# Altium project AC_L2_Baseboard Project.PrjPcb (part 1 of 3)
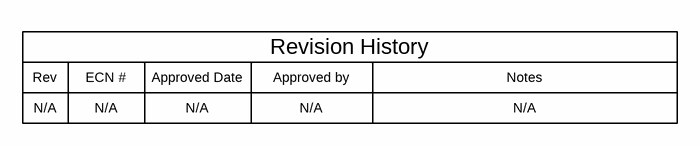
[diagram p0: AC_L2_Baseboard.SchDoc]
CopyrightYear: 2022; EVM_Orderable: N/A; PCB_Layout: R. Scibilia; PCB_Rev: C; PRJ_Engineer: R. Scibilia; PRJ_Number: PMP31161; PRJ_Title: 3-phase Flyback + POL and LDO; SCH_Rev: C; TechSupport: http://www.ti.com/support; TID: TIDA-010239
11 sheets, 511 parts. Net scope: flat (ports and power ports of the same name join across sheets).
Board file: AC_L2_Baseboard PCB.PcbDoc
Sheets:
  AC_L2_Baseboard.SchDoc
  AC_L2_Baseboard SCH-Flyback_PWR.SchDoc
  AC_L2_Baseboard SCH-POL_PWR.SchDoc
  AC_L2_Baseboard_Relay_Weld_Detect.SchDoc
  AC_L2_Baseboard_HPGP_ZC.SchDoc
  AC_L2_Baseboard_Pilot_Wire_ADC.SchDoc
  AC_L2_Baseboard_PlugLock.SchDoc
  AC_L2_Baseboard_RCD.SchDoc
  AC_L2_Baseboard_RCD_MCU.SchDoc
  AC_L2_Baseboard_Connectors.SchDoc
  AC_L2_Baseboard_Hardware.SchDoc

## Sheet AC_L2_Baseboard.SchDoc
size 431 x 279 mm; Date: Not shown in title block; ApprovedBy: Not shown in title block; CheckedBy: Not shown in title block; Author: Not shown in title block; CompanyName: Not shown in title block; Engineer: Not shown in title block; Organization: Not shown in title block; Address1: Not shown in title block; Address2: Not shown in title block; Address3: Not shown in title block; Address4: Not shown in title block; DocumentNumber: 1; Revision: Use project parameter SCH_Rev; SheetNumber: 1; SheetTotal: 11; PageSetup: Record=PageOptions¦CenterHorizontal=True¦CenterVertical=True¦PrintScale=1.00¦XCorrection=1.00¦YCorrection=1.00¦PrintKind=0¦BorderSize=5000000¦LeftOffset=0¦BottomOffset=0¦Orientation=2¦PaperLength=1000¦PaperWidth=1000¦Scale=100¦PaperSource=15¦PrintQuality=600¦MediaType=1¦DitherType=10¦PaperKind=Letter¦PrintScaleMode=1

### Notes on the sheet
- Rev
- N/A
- ECN #
- Approved Date
- Approved by
- Revision History
- Notes

## Sheet AC_L2_Baseboard SCH-Flyback_PWR.SchDoc
size 431 x 279 mm; Date: Not shown in title block; ApprovedBy: Not shown in title block; CheckedBy: Not shown in title block; Author: Not shown in title block; CompanyName: Not shown in title block; Engineer: Not shown in title block; Organization: Not shown in title block; Address1: Not shown in title block; Address2: Not shown in title block; Address3: Not shown in title block; Address4: Not shown in title block; DocumentNumber: 2; Revision: Use project parameter SCH_Rev; SheetNumber: 2; SheetTotal: 11; PageSetup: Record=PageOptions¦CenterHorizontal=True¦CenterVertical=True¦PrintScale=1.00¦XCorrection=1.00¦YCorrection=1.00¦PrintKind=0¦BorderSize=5000000¦LeftOffset=0¦BottomOffset=0¦Orientation=2¦PaperLength=1000¦PaperWidth=1000¦Scale=100¦PaperSource=15¦PrintQuality=600¦MediaType=1¦DitherType=10¦PaperKind=Letter¦PrintScaleMode=1
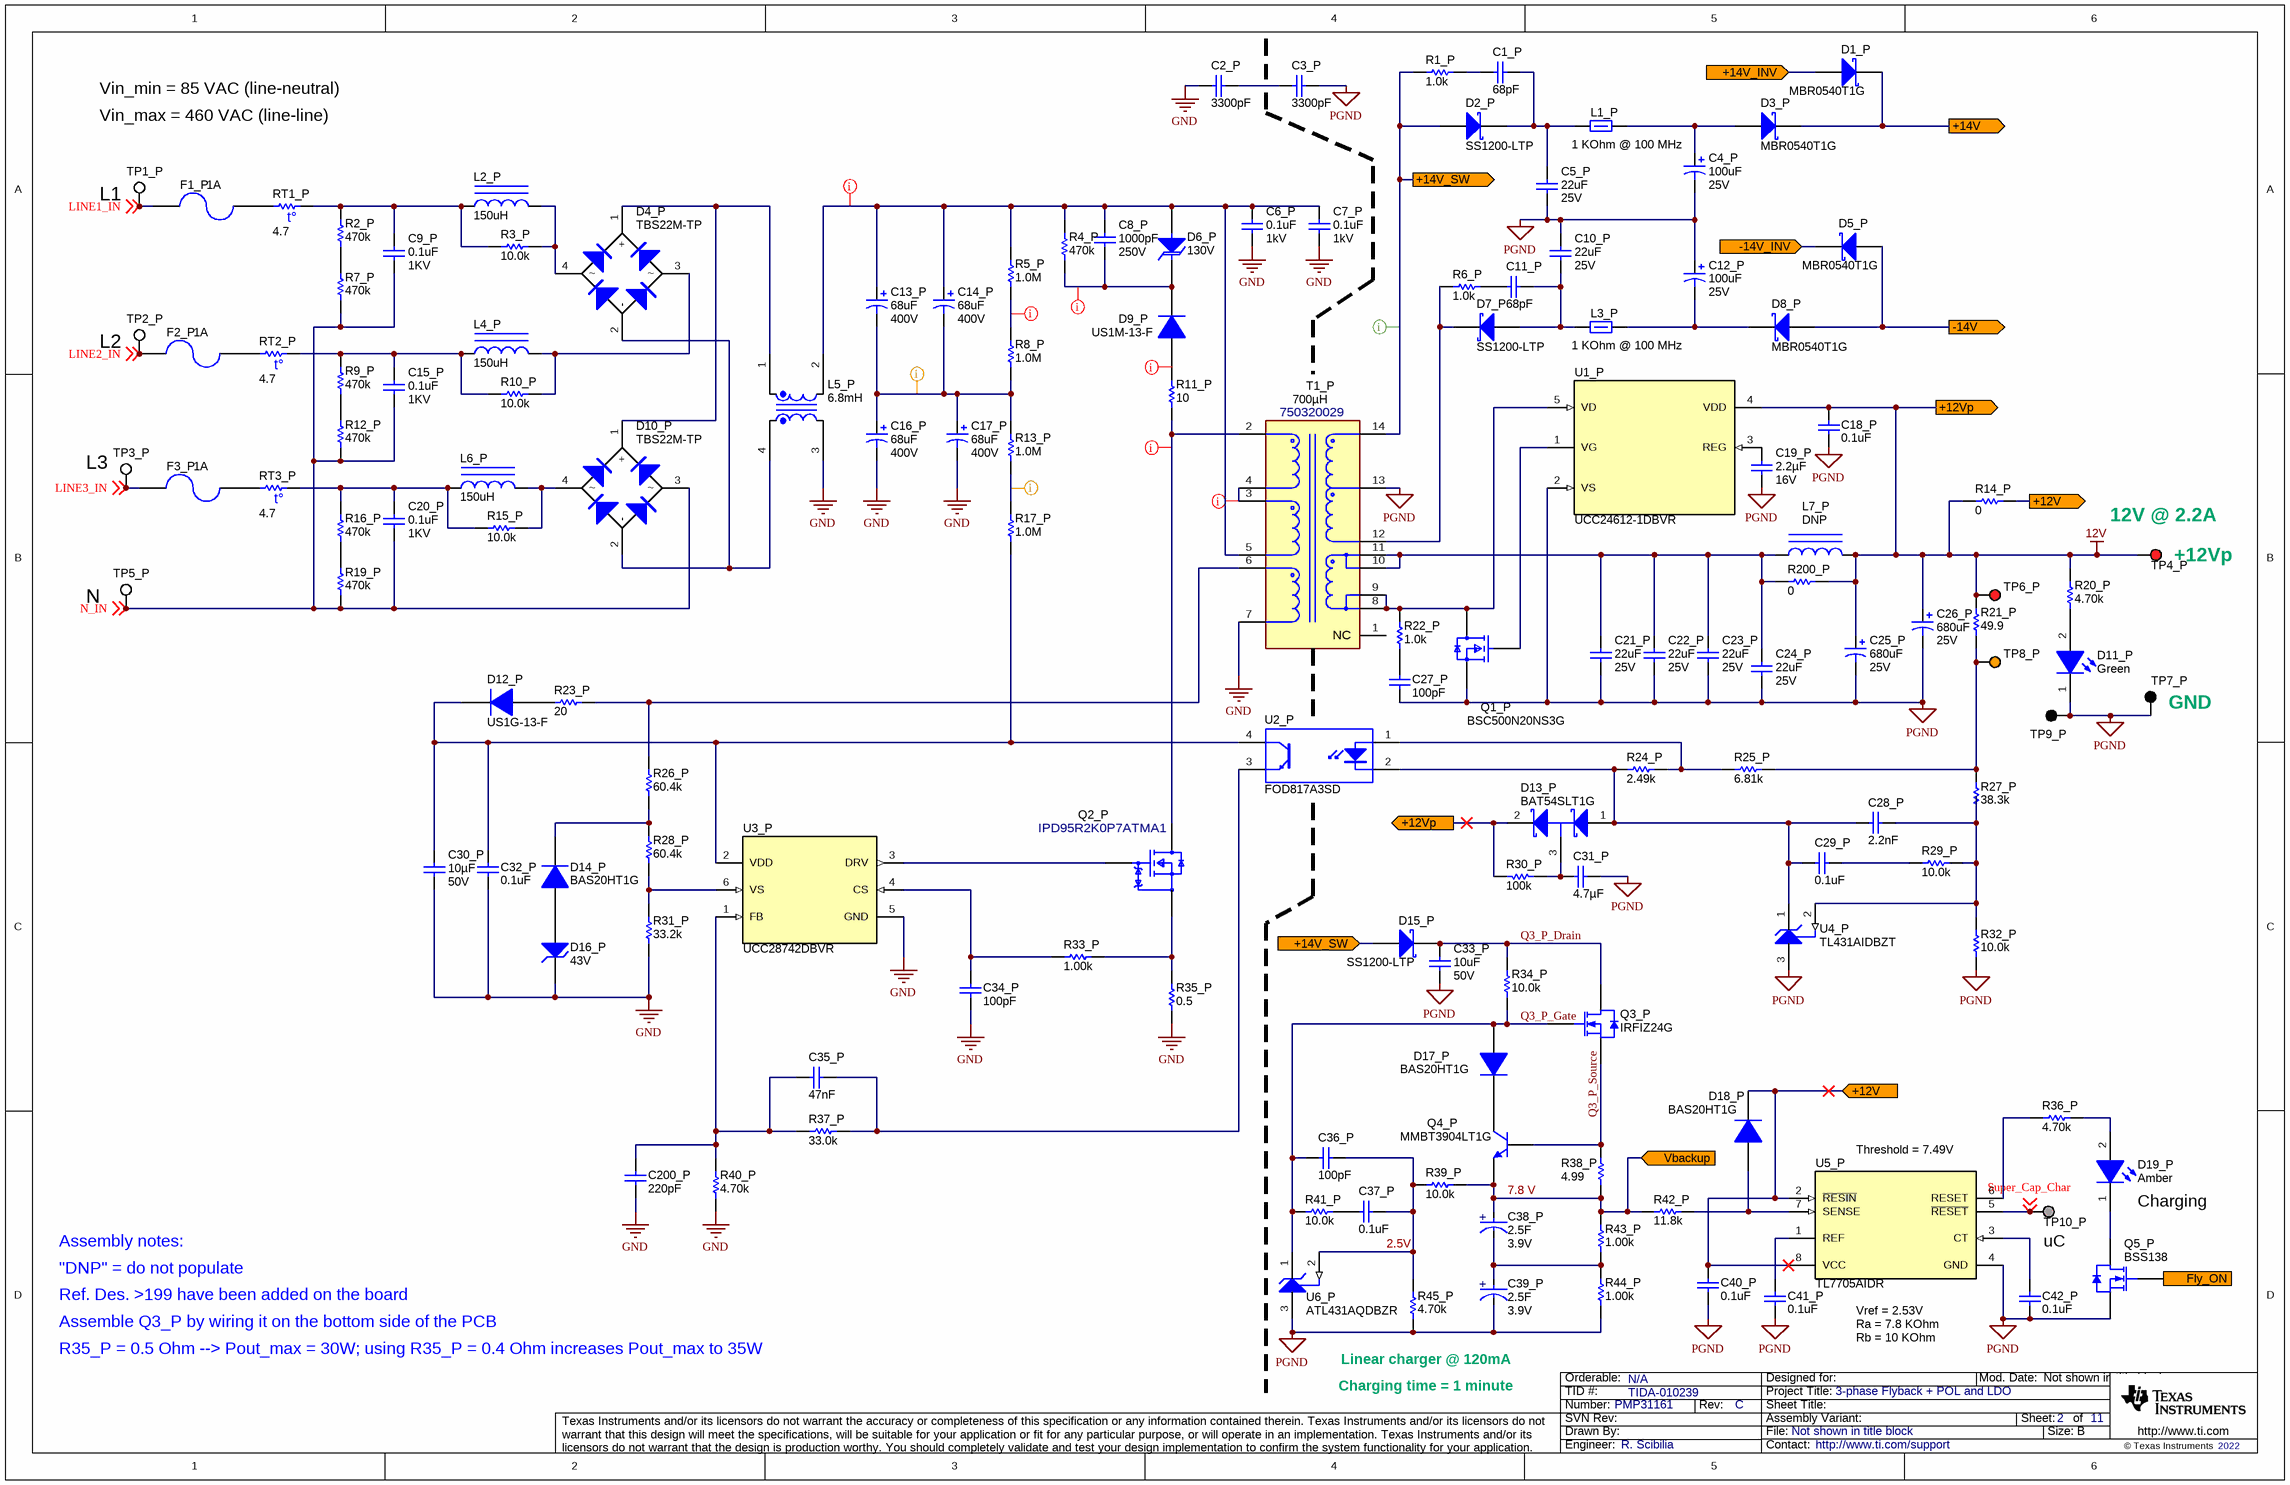
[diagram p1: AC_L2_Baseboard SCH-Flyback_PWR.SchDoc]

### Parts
C1_P  ValueDisplayed: 68pF  [0805_HV]  (hidden comment: GRM21A5C2E680JW01D)
C2_P  ValueDisplayed: 3300pF  [KX_1000x700]  (hidden comment: DE1E3KX332MN4AP01F)
C3_P  ValueDisplayed: 3300pF  [KX_1000x700]  (hidden comment: DE1E3KX332MN4AP01F)
C4_P  VDC_V: 25V  ValueDisplayed: 100uF  [Chemi-Con_630X1100]  (hidden comment: 860010473007)
C5_P  VDC_V: 25V  ValueDisplayed: 22uF  [1210_270]  (hidden comment: 885012109015)
C6_P  VDC_V: 1kV  ValueDisplayed: 0.1uF  [1812_254]  (hidden comment: C1812C104KDRAC7800)
C7_P  VDC_V: 1kV  ValueDisplayed: 0.1uF  [1812_254]  (hidden comment: C1812C104KDRAC7800)
C8_P  value 1000pF  VDC_V: 250V  [0805_HV]  (hidden comment: 885342207008)
C9_P  value 0.1uF  VDC_V: 1KV  [B32672P_1800x850x1450]  (hidden comment: 890493425009CS)
C10_P  VDC_V: 25V  ValueDisplayed: 22uF  [1210_270]  (hidden comment: 885012109015)
C11_P  ValueDisplayed: 68pF  [0805_HV]  (hidden comment: GRM21A5C2E680JW01D)
C12_P  VDC_V: 25V  ValueDisplayed: 100uF  [Chemi-Con_630X1100]  (hidden comment: 860010473007)
C13_P  VDC_V: 400V  ValueDisplayed: 68uF  [HW_1600x2500]  (hidden comment: 860021380017)
C14_P  VDC_V: 400V  ValueDisplayed: 68uF  [HW_1600x2500]  (hidden comment: 860021380017)
C15_P  value 0.1uF  VDC_V: 1KV  [B32672P_1800x850x1450]  (hidden comment: 890493425009CS)
C16_P  VDC_V: 400V  ValueDisplayed: 68uF  [HW_1600x2500]  (hidden comment: 860021380017)
C17_P  VDC_V: 400V  ValueDisplayed: 68uF  [HW_1600x2500]  (hidden comment: 860021380017)
C18_P  value 0.1uF  [0603]  (hidden comment: 885012206095)
C19_P  VDC_V: 16V  Cap_F: 2.2µF  [0603S]  (hidden comment: GRM188Z71C225KE43)
C20_P  value 0.1uF  VDC_V: 1KV  [B32672P_1800x850x1450]  (hidden comment: 890493425009CS)
C21_P  VDC_V: 25V  ValueDisplayed: 22uF  [1210_270]  (hidden comment: 885012109015)
C22_P  VDC_V: 25V  ValueDisplayed: 22uF  [1210_270]  (hidden comment: 885012109015)
C23_P  VDC_V: 25V  ValueDisplayed: 22uF  [1210_270]  (hidden comment: 885012109015)
C24_P  VDC_V: 25V  ValueDisplayed: 22uF  [1210_270]  (hidden comment: 885012109015)
C25_P  VDC_V: 25V  ValueDisplayed: 680uF  [Chemi-Con_1000x2000]  (hidden comment: 860040475009)
C26_P  VDC_V: 25V  ValueDisplayed: 680uF  [Chemi-Con_1000x2000]  (hidden comment: 860040475009)
C27_P  ValueDisplayed: 100pF  [0805_HV]  (hidden comment: GRM21A5C2E101JW01D)
C28_P  Cap_F: 2.2nF  [0603]  (hidden comment: 885012206085)
C29_P  value 0.1uF  [0603]  (hidden comment: 885012206095)
C30_P  VDC_V: 50V  ValueDisplayed: 10µF  [1206_190]  (hidden comment: 885012108022)
C31_P  Cap_F: 4.7µF  [0805_HV]  (hidden comment: 885012107018)
C32_P  value 0.1uF  [0603]  (hidden comment: 885012206095)
C33_P  VDC_V: 50V  ValueDisplayed: 10uF  [1206]  (hidden comment: 885012108022)
C34_P  value 100pF  [0603]  (hidden comment: 885012006057)
C35_P  Cap_F: 47nF  [0603]  (hidden comment: 885012206093)
C36_P  value 100pF  [0603]  (hidden comment: 885012006057)
C37_P  value 0.1uF  [0603]  (hidden comment: 885012206095)
C38_P  VDC_V: 3.9V  ValueDisplayed: 2.5F  [FP-PHVL-3R9V255-R_RADIAL-MFG]  (hidden comment: PHVL-3R9V255-R)
C39_P  VDC_V: 3.9V  ValueDisplayed: 2.5F  [FP-PHVL-3R9V255-R_RADIAL-MFG]  (hidden comment: PHVL-3R9V255-R)
C40_P  value 0.1uF  [0603]  (hidden comment: 885012206095)
C41_P  value 0.1uF  [0603]  (hidden comment: 885012206095)
C42_P  value 0.1uF  [0603]  (hidden comment: 885012206095)
C200_P  ValueDisplayed: 220pF  [0603]  (hidden comment: C0603C221J5GACTU)
D1_P  MBR0540T1G  [SOD-123]
D2_P  SS1200-LTP  [SMA]
D3_P  MBR0540T1G  [SOD-123]
D4_P  TBS22M-TP  [TBS4]
D5_P  MBR0540T1G  [SOD-123]
D6_P  value 130V  [SMC]  (hidden comment: SMCJ130A-TR)
D7_P  SS1200-LTP  [SMA]
D8_P  MBR0540T1G  [SOD-123]
D9_P  US1M-13-F  [SMA]
D10_P  TBS22M-TP  [TBS4]
D11_P  value Green  [WL_SMCW_RED_1206]  (hidden comment: 150120GS75000)
D12_P  US1G-13-F  [SMA]
D13_P  BAT54SLT1G  [SOT-23]
D14_P  BAS20HT1G  [SOD-323]
D15_P  SS1200-LTP  [SMA]
D16_P  value 43V  [SOD-323]  (hidden comment: BZX384C43-E3-08)
D17_P  BAS20HT1G  [SOD-323]
D18_P  BAS20HT1G  [SOD-323]
D19_P  value Amber  [WL_SMCW_RED_1206]  (hidden comment: 150120AS75000)
F1_P  Irating_A: 1A  [FUSE_0443]  (hidden comment: 0443001.DR)
F2_P  Irating_A: 1A  [FUSE_0443]  (hidden comment: 0443001.DR)
F3_P  Irating_A: 1A  [FUSE_0443]  (hidden comment: 0443001.DR)
L1_P  value 1 KOhm @ 100 MHz  [0805_HV]  (hidden comment: 74279205)
L2_P  value 150uH  [WE-TI_1014]  (hidden comment: 7447480151)
L3_P  value 1 KOhm @ 100 MHz  [0805_HV]  (hidden comment: 74279205)
L4_P  value 150uH  [WE-TI_1014]  (hidden comment: 7447480151)
L5_P  value 6.8mH  [Wurth_7446120047]  (hidden comment: 7446121007)
L6_P  value 150uH  [WE-TI_1014]  (hidden comment: 7447480151)
L7_P  DNP  [WE-PD2-S]
Q1_P  BSC500N20NS3G  [FP-BSC220N20NSFDATMA1_TSON-8-MFG]
Q2_P  IPD95R2K0P7ATMA1  [FP-IPD95R2K0P7ATMA1_DPAK-MFG]
Q3_P  IRFIZ24G  [TO-220FP]
Q4_P  MMBT3904LT1G  [SOT-23]
Q5_P  BSS138  [SOT-23]
R1_P  ValueDisplayed: 1.0k  [0805_HV]  (hidden comment: ERJ-6GEYJ102V)
R2_P  ValueDisplayed: 470k  [1206]  (hidden comment: CRCW1206470KJNEA)
R3_P  ValueDisplayed: 10.0k  [0805_HV]  (hidden comment: CRCW080510K0FKEA)
R4_P  ValueDisplayed: 470k  [1206]  (hidden comment: CRCW1206470KJNEA)
R5_P  ValueDisplayed: 1.0M  [1206]  (hidden comment: CRCW12061M00JNEA)
R6_P  ValueDisplayed: 1.0k  [0805_HV]  (hidden comment: ERJ-6GEYJ102V)
R7_P  ValueDisplayed: 470k  [1206]  (hidden comment: CRCW1206470KJNEA)
R8_P  ValueDisplayed: 1.0M  [1206]  (hidden comment: CRCW12061M00JNEA)
R9_P  ValueDisplayed: 470k  [1206]  (hidden comment: CRCW1206470KJNEA)
R10_P  ValueDisplayed: 10.0k  [0805_HV]  (hidden comment: CRCW080510K0FKEA)
R11_P  ValueDisplayed: 10  [1206]  (hidden comment: CRCW120610R0JNEA)
R12_P  ValueDisplayed: 470k  [1206]  (hidden comment: CRCW1206470KJNEA)
R13_P  ValueDisplayed: 1.0M  [1206]  (hidden comment: CRCW12061M00JNEA)
R14_P  ValueDisplayed: 0  [1206]  (hidden comment: RC1206JR-070RL)
R15_P  ValueDisplayed: 10.0k  [0805_HV]  (hidden comment: CRCW080510K0FKEA)
R16_P  ValueDisplayed: 470k  [1206]  (hidden comment: CRCW1206470KJNEA)
R17_P  ValueDisplayed: 1.0M  [1206]  (hidden comment: CRCW12061M00JNEA)
R19_P  ValueDisplayed: 470k  [1206]  (hidden comment: CRCW1206470KJNEA)
R20_P  ValueDisplayed: 4.70k  [0603]  (hidden comment: RC0603FR-074K7L)
R21_P  ValueDisplayed: 49.9  [0603]  (hidden comment: CRCW060349R9FKEA)
R22_P  ValueDisplayed: 1.0k  [1206]  (hidden comment: CRCW12061K00JNEA)
R23_P  ValueDisplayed: 20  [0805_HV]  (hidden comment: CRCW080520R0JNEA)
R24_P  ValueDisplayed: 2.49k  [0603]  (hidden comment: CRCW06032K49FKEA)
R25_P  ValueDisplayed: 6.81k  [0603]  (hidden comment: RC0603FR-076K81L)
R26_P  ValueDisplayed: 60.4k  [0805_HV]  (hidden comment: ERJ-6ENF6042V)
R27_P  ValueDisplayed: 38.3k  [0603]  (hidden comment: RC0603FR-0738K3L)
R28_P  ValueDisplayed: 60.4k  [0805_HV]  (hidden comment: ERJ-6ENF6042V)
R29_P  ValueDisplayed: 10.0k  [0603]  (hidden comment: RC0603FR-0710KL)
R30_P  ValueDisplayed: 100k  [0603]  (hidden comment: CRCW0603100KFKEA)
R31_P  ValueDisplayed: 33.2k  [0603]  (hidden comment: RC0603FR-0733K2L)
R32_P  ValueDisplayed: 10.0k  [0603]  (hidden comment: RC0603FR-0710KL)
R33_P  ValueDisplayed: 1.00k  [0603]  (hidden comment: CRCW06031K00FKEA)
R34_P  ValueDisplayed: 10.0k  [0603]  (hidden comment: RC0603FR-0710KL)
R35_P  ValueDisplayed: 0.5  [2010]  (hidden comment: CSRN2010FKR500)
R36_P  ValueDisplayed: 4.70k  [0603]  (hidden comment: RC0603FR-074K7L)
R37_P  ValueDisplayed: 33.0k  [0603]  (hidden comment: RC0603FR-0733KL)
R38_P  ValueDisplayed: 4.99  [0603]  (hidden comment: CRCW06034R99FKEA)
R39_P  ValueDisplayed: 10.0k  [0603]  (hidden comment: RC0603FR-0710KL)
R40_P  ValueDisplayed: 4.70k  [0603]  (hidden comment: RC0603FR-074K7L)
R41_P  ValueDisplayed: 10.0k  [0603]  (hidden comment: RC0603FR-0710KL)
R42_P  ValueDisplayed: 11.8k  [0603]  (hidden comment: RC0603FR-0711K8L)
R43_P  ValueDisplayed: 1.00k  [0603]  (hidden comment: CRCW06031K00FKEA)
R44_P  ValueDisplayed: 1.00k  [0603]  (hidden comment: CRCW06031K00FKEA)
R45_P  ValueDisplayed: 4.70k  [0603]  (hidden comment: RC0603FR-074K7L)
R200_P  ValueDisplayed: 0  [1206]  (hidden comment: RC1206JR-070RL)
RT1_P  value 4.7  [S153]  (hidden comment: B57153S0479M051)
RT2_P  value 4.7  [S153]  (hidden comment: B57153S0479M051)
RT3_P  value 4.7  [S153]  (hidden comment: B57153S0479M051)
T1_P  750320029  value 700µH  [FP-750320029_PTH14_32MM25_27MM05-MFG]
TP1_P  5012  [Keystone5012]  (value not drawn)
TP2_P  5012  [Keystone5012]  (value not drawn)
TP3_P  5012  [Keystone5012]  (value not drawn)
TP4_P  5010  [Keystone5010]  (value not drawn)
TP5_P  5012  [Keystone5012]  (value not drawn)
TP6_P  5000  [Keystone5000]  (value not drawn)
TP7_P  5011  [Keystone5011]  (value not drawn)
TP8_P  5003  [Keystone5003]  (value not drawn)
TP9_P  5001  [Keystone5001]  (value not drawn)
TP10_P  TP_SM_1MM  [TP_SM_1MM]  (value not drawn)  (no BOM)
U1_P  UCC24612-1DBVR  [DBV0005A_N]
U2_P  FOD817A3SD  [N04C]
U3_P  UCC28742DBVR  [DBV0006A_N]
U4_P  TL431AIDBZT  [DBZ0003A_N]
U5_P  TL7705AIDR  [D0008A_N]
U6_P  ATL431AQDBZR  [DBZ0003A_N]

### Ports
+12V (in), +12V (out), +12Vp (out), +14V (out), +14V_INV (in), +14V_SW (in), +14V_SW (out), -14V (out), -14V_INV (in), Fly_ON (in), Vbackup (in)

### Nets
12V: C18_P.1 C25_P.1(+) C26_P.1(+) D13_P.2(K) L7_P.2 R14_P.1 R20_P.2 R21_P.2 R30_P.1 R200_P.2 TP4_P.1 TP6_P.1 U1_P.4(VDD) ; port +12Vp  [project net 12V_In]
GND: C2_P.2 C6_P.2 C7_P.2 C16_P.2(-) C17_P.2(-) C30_P.2 C32_P.2 C34_P.2 C200_P.1 D16_P.1(K) L5_P.3 R31_P.1 R35_P.1 R40_P.1 T1_P.7 U3_P.5(GND)
PGND: C3_P.1 C4_P.2(-) C5_P.2 C10_P.1 C12_P.1(+) C18_P.2 C19_P.2 C21_P.2 C22_P.2 C23_P.2 C24_P.2 C25_P.2(-) C26_P.2(-) C27_P.2 C31_P.2 C33_P.2 C39_P.1(CATHODE) C40_P.2 C41_P.2 C42_P.2 D11_P.1(K) Q1_P.1-2-3(S) Q5_P.2(S) R32_P.1 R44_P.1 R45_P.1 T1_P.13 TP7_P.1 TP9_P.1 U1_P.2(VS) U4_P.3(ANODE) U5_P.4(GND) U6_P.3(ANODE)
+12V: C40_P.1 D18_P.1(K) R14_P.2 U5_P.2(~{RESIN}) U5_P.8(VCC) ; port +12V
+14V: D1_P.1(K) D3_P.1(K) ; port +14V
+14V_INV: D1_P.2(A) ; port +14V_INV
+14V_SW: D2_P.2(A) D15_P.2(A) R1_P.1 T1_P.14 ; port +14V_SW
-14V: D5_P.2(A) D8_P.2(A) ; port -14V
-14V_INV: D5_P.1(K) ; port -14V_INV
Fly_ON: Q5_P.1(G) ; port Fly_ON
LINE1_IN: F1_P.2 TP1_P.1 ; off-sheet LINE1_IN
LINE2_IN: F2_P.2 TP2_P.1 ; off-sheet LINE2_IN
LINE3_IN: F3_P.2 TP3_P.1 ; off-sheet LINE3_IN
N_IN: C9_P.2 C15_P.2 C20_P.2 D10_P.3 R7_P.1 R12_P.1 R19_P.1 TP5_P.1 ; off-sheet N_IN
Q3_P_Drain: C33_P.1 D15_P.1(K) Q3_P.2(D) R34_P.1
Q3_P_Gate: C36_P.1 D17_P.2(A) Q3_P.1(G) R34_P.2 R41_P.1 U6_P.1(CATHODE)
Q3_P_Source: Q3_P.3(S) Q4_P.1(B) R38_P.2
Super_Cap_Char: TP10_P.1 U5_P.5(~{RESET}) ; off-sheet Super_Cap_Char
Vbackup: C38_P.2(ANODE) Q4_P.2(E) R38_P.1 R39_P.1 R42_P.1 R43_P.2 ; port Vbackup
NetC1_P_1: C1_P.1 C5_P.1 D2_P.1(K) L1_P.1
NetC1_P_2: C1_P.2 R1_P.2
NetC2_P_1: C2_P.1 C3_P.2
NetC4_P_1: C4_P.1(+) D3_P.2(A) L1_P.2
NetC6_P_1: C6_P.1 C7_P.1 C8_P.1 C13_P.1(+) C14_P.1(+) D6_P.2(A) L5_P.2 R4_P.2 R5_P.2 T1_P.5
NetC8_P_2: C8_P.2 D6_P.1(K) D9_P.1(K) R4_P.1
NetC9_P_1: C9_P.1 L2_P.1 R2_P.2 R3_P.1 RT1_P.2
NetC10_P_2: C10_P.2 C11_P.1 D7_P.2(A) L3_P.1
NetC11_P_2: C11_P.2 R6_P.2
NetC12_P_2: C12_P.2(-) D8_P.1(K) L3_P.2
NetC13_P_2: C13_P.2(-) C14_P.2(-) C16_P.1(+) C17_P.1(+) R8_P.1 R13_P.2
NetC15_P_1: C15_P.1 L4_P.1 R9_P.2 R10_P.1 RT2_P.2
NetC19_P_1: C19_P.1 U1_P.3(REG)
NetC20_P_1: C20_P.1 L6_P.1 R15_P.1 R16_P.2 RT3_P.2
NetC21_P_1: C21_P.1 C22_P.1 C23_P.1 C24_P.1 L7_P.1 R200_P.1 T1_P.10 T1_P.11
NetC27_P_1: C27_P.1 R22_P.1
NetC28_P_1: C28_P.1 C29_P.1 D13_P.1(A) R24_P.2 U2_P.2(K) U4_P.1(CATHODE)
NetC28_P_2: C28_P.2 R27_P.1 R29_P.2 R32_P.2 U4_P.2(REF)
NetC29_P_2: C29_P.2 R29_P.1
NetC30_P_1: C30_P.1 C32_P.1 D12_P.1(K) R17_P.1 U2_P.4(C) U3_P.2(VDD)
NetC31_P_1: C31_P.1 D13_P.3(C) R30_P.2
NetC34_P_1: C34_P.1 R33_P.1 U3_P.4(CS)
NetC35_P_1: C35_P.1 R37_P.2 U2_P.3(E)
NetC35_P_2: C35_P.2 C200_P.2 R37_P.1 R40_P.2 U3_P.1(FB)
NetC36_P_2: C36_P.2 C37_P.2 R39_P.2 R45_P.2 U6_P.2(REF)
NetC37_P_1: C37_P.1 R41_P.2
NetC38_P_1: C38_P.1(CATHODE) C39_P.2(ANODE) R43_P.1 R44_P.2
NetC41_P_1: C41_P.1 U5_P.1(REF)
NetC42_P_1: C42_P.1 U5_P.3(CT)
NetD4_P_1: D4_P.1(+) D10_P.1(+) L5_P.1
NetD4_P_2: D4_P.2(-) D10_P.2(-) L5_P.4
NetD4_P_3: D4_P.3 L4_P.2 R10_P.2
NetD4_P_4: D4_P.4 L2_P.2 R3_P.2
NetD7_P_1: D7_P.1(K) R6_P.1 T1_P.12
NetD9_P_2: D9_P.2(A) R11_P.2
NetD10_P_4: D10_P.4 L6_P.2 R15_P.2
NetD11_P_2: D11_P.2(A) R20_P.1
NetD12_P_2: D12_P.2(A) R23_P.1
NetD14_P_1: D14_P.1(K) R26_P.1 R28_P.2
NetD14_P_2: D14_P.2(A) D16_P.2(A)
NetD17_P_1: D17_P.1(K) Q4_P.3(C)
NetD18_P_2: D18_P.2(A) R42_P.2 U5_P.7(SENSE)
NetD19_P_1: D19_P.1(K) Q5_P.3(D)
NetD19_P_2: D19_P.2(A) R36_P.1
NetF1_P_1: F1_P.1 RT1_P.1
NetF2_P_1: F2_P.1 RT2_P.1
NetF3_P_1: F3_P.1 RT3_P.1
NetQ1_P_4: Q1_P.4(G) U1_P.1(VG)
NetQ1_P_5-6-7-8: Q1_P.5-6-7-8(D) R22_P.2 T1_P.8 T1_P.9 U1_P.5(VD)
NetQ2_P_1: Q2_P.1(Gate) U3_P.3(DRV)
NetQ2_P_3: Q2_P.3(Source) R33_P.2 R35_P.2
NetQ2_P_4: Q2_P.4(Drain) R11_P.1 T1_P.2
NetR2_P_1: R2_P.1 R7_P.2
NetR5_P_1: R5_P.1 R8_P.2
NetR9_P_1: R9_P.1 R12_P.2
NetR13_P_1: R13_P.1 R17_P.2
NetR16_P_1: R16_P.1 R19_P.2
NetR21_P_1: R21_P.1 R25_P.2 R27_P.2 TP8_P.1
NetR23_P_2: R23_P.2 R26_P.2 T1_P.6
NetR24_P_1: R24_P.1 R25_P.1 U2_P.1(A)
NetR28_P_1: R28_P.1 R31_P.2 U3_P.6(VS)
NetR36_P_2: R36_P.2 U5_P.6(RESET)
NetT1_P_3: T1_P.3 T1_P.4

Not connected (* = marked no-connect by the designer): T1_P 1(NC)

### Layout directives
rule Clearance Constraint [Clearance = 30mil]: NetC6_P_1
rule Clearance Constraint [Clearance = 20mil]: NetC13_P_2, NetR13_P_1
rule Clearance Constraint [Clearance = 40mil]: NetC8_P_2, NetD9_P_2, NetQ2_P_4, NetR5_P_1, NetT1_P_3
rule Clearance Constraint [Clearance = 10mil]: +14V_SW

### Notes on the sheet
- Vin_min = 85 VAC (line-neutral)
- Vin_max = 460 VAC (line-line)
- (near TP1_P) L1
- (near TP2_P) L2
- (near TP3_P) L3
- (near TP4_P) 12V @ 2.2A
- (near TP4_P) +12Vp
- (near TP5_P) N
- (near TP7_P) GND
- (near U5_P) Threshold = 7.49V
- 7.8 V
- (near D19_P) Charging
- Assembly notes:
- Ref. Des. >199 have been added on the board
- "DNP" = do not populate
- 2.5V
- (near TP10_P) uC
- Assemble Q3_P by wiring it on the bottom side of the PCB
- R35_P = 0.5 Ohm --> Pout_max = 30W; using R35_P = 0.4 Ohm increases Pout_max to 35W
- (near R45_P) Linear charger @ 120mA
- (near U5_P) Vref = 2.53V
- Ra = 7.8 KOhm
- Rb = 10 KOhm
- Charging time = 1 minute

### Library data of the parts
C1_P C11_P = CMP-0008246-2: CAP, CERM, 68 pF, 250 V, +/- 5%, C0G/NP0, 0805; Manufacturer: MuRata; TaMin_C: -55°C; Polarized: N; SizeAreaWB_mm2: 6.75; Value1: Unknown; U/M: EA; Value: 68pF; TaMax_C: 125°C; SizeZ_mm: 1.45; SizeX_mm: 2; SizeY_mm: 1.25; Cap_Case: 0805; Value2: 250V; SizeArea_mm2: 2.5; AEC Category: Q200
C2_P C3_P = CMP-0009604-2: CAP, CERM, 3300 pF, 300 V, +/- 20%, E, D10xT7mm; Manufacturer: MuRata; TaMin_C: -40°C; Polarized: N; SizeAreaWB_mm2: 108; Value1: Unknown; U/M: EA; Value: 3300pF; TaMax_C: 125°C; SizeZ_mm: 13; SizeX_mm: 10; SizeY_mm: 7; Cap_Case: 10x7mm; Value2: 300V; SizeArea_mm2: 70; Cap_F: 3.3nF; AEC Category: Q200
C4_P C12_P = CMP-0010399-1: CAP, AL, 100 uF, 25 V, +/- 20%, TH; Manufacturer: Wuerth; TaMin_C: -40°C; Polarized: Y; SizeAreaWB_mm2: 68.89; Value1: Unknown; U/M: EA; Value: 100uF; TaMax_C: 105°C; SizeZ_mm: 12.5; SizeX_mm: 6.3; Cap_Case: 6.3x11; SizeArea_mm2: 39.69; CompType: Capacitor; AEC Qualified: N; Cap_F: 100µF; IRMS_A: 300mA; AEC Category: Q200
C5_P C10_P C21_P C22_P C23_P C24_P = CMP-0009224-2: CAP, CERM, 22 uF, 25 V, +/- 20%, X5R, 1210; Manufacturer: Wuerth; TaMin_C: -55°C; Polarized: N; SizeAreaWB_mm2: 14.7; Value1: Unknown; U/M: EA; Value: 22uF; TaMax_C: 85°C; SizeZ_mm: 2.7; SizeX_mm: 3.2; SizeY_mm: 2.5; Cap_Case: 1210; SizeArea_mm2: 8; Cap_F: 22µF; AEC Category: Q200
C6_P C7_P = CMP-0009326-2: CAP, CERM, 0.1 uF, 1000 V, +/- 10%, X7R, 1812; Manufacturer: Kemet; TaMin_C: -55°C; Polarized: N; SizeAreaWB_mm2: 23.1; Value1: Unknown; U/M: EA; Value: 0.1uF; TaMax_C: 125°C; SizeZ_mm: 2.54; SizeX_mm: 4.5; SizeY_mm: 3.2; Cap_Case: 1812; Value2: 1000V; SizeArea_mm2: 14.4; Cap_F: 100nF; AEC Category: Q200
C8_P = CMP-0008251-2: CAP, CERM, 1000 pF, 250 V, +/- 10%, X7R, 0805; Manufacturer: Wuerth; TaMin_C: -55°C; Polarized: N; SizeAreaWB_mm2: 6.75; Value1: Unknown; U/M: EA; TaMax_C: 125°C; SizeZ_mm: 1.45; SizeX_mm: 2; SizeY_mm: 1.25; Cap_Case: 0805; SizeArea_mm2: 2.5; Cap_F: 1nF; AEC Category: Q200
C9_P C15_P C20_P = CMP-0860409-1: CAP, Film, 0.1 µF, 1000 VDC,+/- 10%, TH; Manufacturer: Wuerth; SizeY_mm: 8.5; AEC Category: Q200; AEC Qualified: N; Cap_Case: 18x8.5x15mm; ValueDisplayed: 0.1µF; SizeArea_mm2: 153; SizeAreaWB_mm2: 210; SizeX_mm: 18; SizeZ_mm: 15; TaMin_C: -55°C; TaMax_C: 85°C; Cap_F: 100nF
C13_P C14_P C16_P C17_P = CMP-0009928-2: CAP, AL, 68 uF, 400 V, +/- 20%, 410 mA @ 120 Hz, TH; Manufacturer: Wuerth; TaMin_C: -40°C; Polarized: Y; SizeAreaWB_mm2: 324; U/M: EA; Value: 68uF; TaMax_C: 105°C; SizeZ_mm: 27; SizeX_mm: 16; Cap_Case: 16x25mm; SizeArea_mm2: 256; CompType: Capacitor; AEC Qualified: N; IRMS_A: 410mA
C18_P C29_P C32_P C37_P C40_P C41_P C42_P = CMP-0007044-5: CAP, CERM, 0.1 uF, 50 V, +/- 10%, X7R, 0603; Manufacturer: Wuerth; TaMin_C: -55°C; ESR_ohm: 29.6m; Polarized: N; SizeAreaWB_mm2: 4.68; Value1: 0.0296 ohm; U/M: EA; TaMax_C: 125°C; SizeZ_mm: 1; SizeX_mm: 1.6; SizeY_mm: 0.8; Value2: 50V; SizeArea_mm2: 1.28; Cap_F: 100nF; IRMS_A: 971.99mA; AEC Category: Q200
C19_P = CMP-0007499-4: CAP, CERM, 2.2 uF, 16 V, +/- 10%, X7R, 0603; Manufacturer: MuRata; TaMin_C: -55°C; Polarized: N; SizeAreaWB_mm2: 4.68; Value1: Unknown; U/M: EA; Value: 2.2uF; TaMax_C: 125°C; SizeZ_mm: 1; SizeX_mm: 1.6; SizeY_mm: 0.8; Cap_Case: 0603; SizeArea_mm2: 1.28; AEC Category: Q200
C25_P C26_P = CMP-0010412-1: CAP, AL, 680 uF, 25 V, +/- 20%, TH; Manufacturer: Wuerth; TaMin_C: -40°C; Polarized: Y; SizeAreaWB_mm2: 144; Value1: Unknown; U/M: EA; Value: 680uF; TaMax_C: 105°C; SizeZ_mm: 21.5; SizeX_mm: 10; Cap_Case: 10x20; SizeArea_mm2: 100; CompType: Capacitor; AEC Qualified: N; Cap_F: 680µF; IRMS_A: 1.4A
C27_P = CMP-0008236-2: CAP, CERM, 100 pF, 250 V, +/- 5%, C0G/NP0, 0805; Manufacturer: MuRata; TaMin_C: -55°C; Polarized: N; SizeAreaWB_mm2: 6.75; Value1: Unknown; U/M: EA; Value: 100pF; TaMax_C: 125°C; SizeZ_mm: 1.45; SizeX_mm: 2; SizeY_mm: 1.25; Cap_Case: 0805; Value2: 250V; SizeArea_mm2: 2.5; AEC Category: Q200
C28_P = CMP-0006897-4: CAP, CERM, 2200 pF, 50 V, +/- 10%, X7R, 0603; Manufacturer: Wuerth; TaMin_C: -55°C; Polarized: N; SizeAreaWB_mm2: 4.68; Value1: Unknown; U/M: EA; Value: 2200pF; TaMax_C: 125°C; SizeZ_mm: 1; SizeX_mm: 1.6; SizeY_mm: 0.8; Value2: 50V; SizeArea_mm2: 1.28; AEC Category: Q200
C30_P = CMP-0086153-1: CAP, CERM, 10 µF, 50 V,+/- 10%, X5R, 1206; Manufacturer: Wuerth; Polarized: N; SizeX_mm: 3.2; TaMax_C: 85°C; SizeY_mm: 1.6; SizeArea_mm2: 5.12; Cap_Case: 1206; SizeAreaWB_mm2: 10.92; TaMin_C: -55°C; SizeZ_mm: 1.9; U/M: EA; Value: 10uF
C31_P = CMP-0007870-2: CAP, CERM, 4.7 uF, 25 V, +/- 20%, X5R, 0805; Manufacturer: Wuerth; TaMin_C: -55°C; Polarized: N; SizeAreaWB_mm2: 6.75; Value1: Unknown; U/M: EA; Value: 4.7uF; TaMax_C: 85°C; SizeZ_mm: 1.45; SizeX_mm: 2; SizeY_mm: 1.25; Cap_Case: 0805; Value2: 25V; SizeArea_mm2: 2.5; AEC Category: Q200
C33_P = CMP-0008821-2: CAP, CERM, 10 uF, 50 V, +/- 10%, X7R, 1206; Manufacturer: Wuerth; TaMin_C: -55°C; Polarized: N; SizeAreaWB_mm2: 10.92; Value1: Unknown; U/M: EA; Value: 10uF; TaMax_C: 125°C; SizeZ_mm: 1.35; SizeX_mm: 3.2; SizeY_mm: 1.6; SizeArea_mm2: 5.12; Cap_F: 10µF; AEC Category: Q200
C34_P C36_P = CMP-0006840-4: CAP, CERM, 100 pF, 50 V, +/- 5%, C0G/NP0, 0603; Manufacturer: Wuerth; TaMin_C: -55°C; Polarized: N; SizeAreaWB_mm2: 4.68; Value1: Unknown; U/M: EA; TaMax_C: 125°C; SizeZ_mm: 1; SizeX_mm: 1.6; SizeY_mm: 0.8; Value2: 50V; SizeArea_mm2: 1.28; AEC Category: Q200
C35_P = CMP-0007049-4: CAP, CERM, 0.047 uF, 50 V, +/- 10%, X7R, 0603; Manufacturer: Wuerth; TaMin_C: -55°C; ESR_ohm: 49.007m; Polarized: N; SizeAreaWB_mm2: 4.68; Value1: 0.049007 ohm; U/M: EA; TaMax_C: 125°C; SizeZ_mm: 1; SizeX_mm: 1.6; SizeY_mm: 0.8; Value2: 50V; SizeArea_mm2: 1.28; IRMS_A: 767.528mA; AEC Category: Q200
C38_P C39_P = CMP-0095175-1: 2.5 F (EDLC) Supercapacitor 3.9 V Radial 80mOhm 5000 Hrs @ 85°C; Manufacturer: Cooper Bussmann; SizeZ_mm: 23.5mm; Value: 2.5F; AEC Qualified: No; Tolerance_%: 30%
C200_P = CMP-0006893-4: CAP, CERM, 220 pF, 50 V, +/- 5%, C0G/NP0, 0603; Manufacturer: Kemet; TaMin_C: -55°C; Polarized: N; SizeAreaWB_mm2: 4.68; Value1: Unknown; U/M: EA; Value: 220pF; TaMax_C: 125°C; SizeZ_mm: 1; SizeX_mm: 1.6; SizeY_mm: 0.8; Value2: 50V; SizeArea_mm2: 1.28; AEC Category: Q200
D1_P D3_P D5_P D8_P = CMP-0028526-2: Diode, Schottky, 40 V, 0.5 A, SOD-123; Manufacturer: ON Semiconductor; Green_REACh: Passed; SizeY_mm: 1.7; Io_A: 500mA; SizeArea_mm2: 6.545; RJC_CperW: 118; Green_Lifecycle: Active; Vr_V: 40V; Vf_V: 510mV; TJmax_C: 150°C; AEC Category: Q101; SizeAreaWB_mm2: 13.095; Value1: 0.5A; SizeZ_mm: 1.35; SizeX_mm: 3.85; Value2: 0.51V
D2_P D7_P D15_P = CMP-0028981-2: Diode, Schottky, 200 V, 1 A, SMA; Manufacturer: Micro Commercial Components; TJmax_C: 150°C; SizeArea_mm2: 16.3228; Io_A: 1A; AEC Qualified: N; SizeX_mm: 5.59; SizeZ_mm: 2.87; Vf_V: 920mV; AEC Category: Q101; Vr_V: 200V; Value2: 0.92V; SizeY_mm: 2.92; SizeAreaWB_mm2: 37.3428
D4_P D10_P = CMP-0029252-2: Diode, Switching-Bridge, 1000 V, 2.2 A, 8.25x6.6mm; Manufacturer: Micro Commercial Components; Io_A: 2.2A; SizeAreaWB_mm2: 88.15; Vr_V: 1kV; TJmax_C: 150°C; U/M: EA; SizeZ_mm: 1.5; SizeX_mm: 8.25; SizeY_mm: 6.6; Vf_V: 1.1V; SizeArea_mm2: 54.45; AEC Qualified: N; AEC Category: Q101; RJC_CperW: 10
D6_P = CMP-0085439-1: Diode, TVS, Uni, 130 V, 209 Vc, 1500 W, 7.5 A, SMC; Manufacturer: STMicroelectronics; Ppk: 1.5kW; SizeY_mm: 6.22; SizeAreaWB_mm2: 83.2686; Vbr_Min: 144V; SizeZ_mm: 2.62; Ipp: 7.5A; AEC Qualified: N; AEC Category: Q101; SizeX_mm: 8.13; Vc: 209V; SizeArea_mm2: 50.5686; RJA_CperW: 90
D9_P = CMP-0076882-1: Diode, Ultrafast, 1000 V, 1 A, SMA; Manufacturer: Diodes Inc.; SizeAreaWB_mm2: 37.3428; Vr_V: 1kV; SizeArea_mm2: 16.3228; TJmax_C: 150°C; AEC Category: Q101; SizeZ_mm: 2.87; Green_REACh: Incomplete; Io_A: 1A; Vf_V: 1.7V; SizeY_mm: 2.92; Green_Lifecycle: Not Set; U/M: EA; SizeX_mm: 5.59; RJC_CperW: 30.0
D11_P = CMP-0002935-3: LED, Green, SMD; Manufacturer: Wurth Elektronik; Vf_V: 2V; Angle: 140; Value1: 0.072W; Vr_V: 5V; Io_A: 20mA; Tjmax_C: 85°C; Type: AlInGaP; Power_TotalModule: 72mW; Ir_A: 10µA
D12_P = CMP-0077026-2: Diode, Ultrafast, 400 V, 1 A, SMA; Manufacturer: Diodes Inc.; SizeY_mm: 2.92; Value1: 1A; SizeAreaWB_mm2: 37.3428; Value2: 1.3V; TJmax_C: 150°C; Green_REACh: Incomplete; Vr_V: 400V; SizeArea_mm2: 16.3228; SizeX_mm: 5.59; SizeZ_mm: 2.87; AEC Category: Q101; Green_Lifecycle: Not Set
D13_P = CMP-0028613-2: Diode, Schottky, 30 V, 0.2 A, SOT-23; Manufacturer: ON Semiconductor; TJmax_C: 150°C; AEC Category: Q101; SizeAreaWB_mm2: 14; Value2: 0.8V; Value1: 0.2A; SizeZ_mm: 1.1; Vf_V: 800mV; Vr_V: 30V; Green_Lifecycle: Not Set; Io_A: 200mA; SizeY_mm: 3; SizeX_mm: 2.5; SizeArea_mm2: 7.5; Green_REACh: Incomplete
D14_P D17_P D18_P = CMP-0029150-2: Diode, Switching, 200 V, 0.2 A, AEC-Q101, SOD-323; Manufacturer: ON Semiconductor; Value2: 1.25V; Value1: 0.2A; SizeZ_mm: 1; Green_REACh: Incomplete; SizeArea_mm2: 3.645; Vr_V: 200V; SizeX_mm: 2.7; TJmax_C: 150°C; Io_A: 200mA; Green_Lifecycle: Not Set; SizeAreaWB_mm2: 8.695; AEC Qualified: Y; AEC Category: Q101; SizeY_mm: 1.35
D16_P = CMP-0005844-3: Diode, Zener, 43 V, 200 mW, SOD-323; Manufacturer: Vishay General Semiconductor; AEC Category: Q101; SizeZ_mm: 1; SizeArea_mm2: 3.645; Power_W: 200mW; RJA_CperW: 415; Value1: 0.2W; SizeX_mm: 2.7; SizeAreaWB_mm2: 8.695; SizeY_mm: 1.35
D19_P = CMP-0002935-3: LED, Amber, SMD; Manufacturer: Wurth Elektronik; Vf_V: 2V; Angle: 140; Value1: 0.072W; Vr_V: 5V; Io_A: 20mA; Tjmax_C: 85°C; Type: AlInGaP; Power_TotalModule: 72mW; Ir_A: 10µA
F1_P F2_P F3_P = CMP-0003467-2: Fuse, 1 A, 250VAC/VDC, SMD; Manufacturer: Littelfuse; Interrupt_AC: 50A; Interrupt_DC: 250A; VAC_V: 250V; Rtyp_Ohm: 0.18; MeltingTyp: 10.17; Value: 1A
L1_P L3_P = CMP-0003090-1: Ferrite Bead, 1000 ohm @ 100 MHz, 0.2 A, 0805; Manufacturer: Wurth Elektronik; Ztyp@1GHz_Ohm: 194.226; ZTyp@100MHz_Ohm: 1k; SizeAreaWB_mm2: 6.75; DCR_ohm: 0.45; Value1: 0.45 ohm; Imax_A: 200mA; SizeZ_mm: 1.45; SizeX_mm: 2; SizeY_mm: 1.25; Value2: 0.2A; SizeArea_mm2: 2.5
L2_P L4_P L6_P = CMP-0064523-2: Inductor, Wirewound, Ferrite, 150 uH, 2 A, 0.16 ohm, TH; Manufacturer: Wurth Elektronik; Isat: 2.1A @ 10% inductance drop; Irms: 2A @ 40C rise; Green_Lifecycle: Active; SizeAreaWB_mm2: 156.25; DCR_ohm: 0.1; Green_REACh: Passed; Imax_A: 2A; SizeZ_mm: 14.5; SizeX_mm: 10.5; SizeArea_mm2: 110.25; Ind_H: 150µH; AEC Category: Q200
L5_P = CMP-0013107-2: Coupled inductor, 6.8 mH, 1 A, 0.3 ohm, TH; Manufacturer: Wurth Elektronik; DCR_ohm: 0.3
L7_P = CMP-0064228-1: Green_Lifecycle: Active; SizeAreaWB_mm2: 27.5; DCR_ohm: 49m; Green_REACh: Passed; Material: Ferrite; SizeZ_mm: 3.2; SizeX_mm: 4; SizeY_mm: 4.5; SizeArea_mm2: 18; CompType: Inductor; AEC Category: Q200
Q1_P = CMP-0089849-1: Mosfet, N-Ch, 200V, 24A, 150Deg C Rohs Compliant: Yes; Manufacturer: Infineon; VdsMax_V: 1.2V; Threshold Vgs Min: 2V; Pulse Drain Current: 97A; QgTyp_nC: 15nC @ 10V; Transconductance: 88S; Vgs_V: 20V; Turn On Delay Time: 7ns; Rthja Max: 75K/W; Threshold Vgs Max: 4V; ChMode: False; Turn Off Delay Time: 28ns; Number Of Channels: 1; AEC Qualified: No; Rdson45_ohm: 42m; Typ Forward Diode Voltage: 1V; Input Capacitace At Vds: 2770pF @ 100V; SizeZ_mm: 1.1mm; TJmax_C: +175°C
Q2_P = CMP-0091039-1: Trans MOSFET N-CH 600V 4A 3-Pin(2+Tab) DPAK T/R; Manufacturer: Infineon Technologies; Drain To Source Breakdown Voltage: 950V; Input Capacitace At Vds: 330pF @ 400V; TJmax_C: +150°C; Turn On Delay Time: 6ns; Turn Off Delay Time: 41ns; Number Of Channels: 1; Rthja Max: 62°C/W; AEC Qualified: No; QgTyp_nC: 10nC @ 10V; Reverse Recovery Charge: 2000nC; Pulse Drain Current: 10A; Power_W: 37W; Typ Forward Diode Voltage: 0.9V; SizeZ_mm: 2.48mm; Threshold Vgs Min: 2.5V; ChMode: False; Reverse Recovery Time: 337ns; Rdson45_ohm: 1.71; Threshold Vgs Max: 3.5V; Vgs_V: 20V
Q3_P = CMP-0001232-1: MOSFET, N-CH, 60 V, 14 A, TO-220FP; Alternate Manufacturer: None; Manufacturer: Vishay; SizeZ_mm: 20; ChType: N; Value2: 24 nC; VdsMax_V: 60V; SizeX_mm: 10.2; SizeY_mm: 4.5; Vgs_V: 20V; QgTyp_nC: 25; Value: 60V; SizeArea_mm2: 45.9; AEC Category: Q101; IdsMax_A: 14A; SizeAreaWB_mm2: 79.3; U/M: EA
Q4_P = CMP-0000419-2: Transistor, NPN, 40 V, 0.2 A, SOT-23; Manufacturer: ON Semiconductor; TaMax_C: 150°C; Value2: 300; Value1: 0.2 A; Vcesat1_V: 300mV; SizeX_mm: 2.5; SizeY_mm: 3; TaMin_C: -55°C; IcRated_A: 200mA; CompType: BJT; SizeZ_mm: 1.1; Value: 40 V; SizeArea_mm2: 7.5; NPN: 1; Vceo_V: 40V; PNP: 0; AEC Category: Q101; SizeAreaWB_mm2: 14; U/M: EA
Q5_P = CMP-0000755-1: MOSFET, N-CH, 50 V, 0.22 A, SOT-23; Alternate Manufacturer: None; Manufacturer: Fairchild Semiconductor; SizeZ_mm: 1.1; ChType: N; Value2: 1.7 nC; VdsMax_V: 50V; SizeX_mm: 2.5; SizeY_mm: 3; Vgs_V: 20V; Rdson45_ohm: 6; SizeArea_mm2: 7.5; AEC Category: Q101; IdsMax_A: 220mA; SizeAreaWB_mm2: 14; U/M: EA; QgTyp_nC: 1.7
R1_P R6_P = CMP-0020619-3: RES, 1.0 k, 5%, 0.125 W, AEC-Q200 Grade 0, 0805; Manufacturer: Panasonic; Power_W: 125mW; TempCo: 200 ppm/C; Value_Code: 1k00; Value: 1.0k; EIA_Code: E24; Res_ohm: 1k; SizeX_mm: 2; SizeY_mm: 1.25; SizeZ_mm: 1.45; Value2: 0.125W; SizeArea_mm2: 2.5; AEC Qualified: Y; VDC_V: 150V; AEC Category: Q200; AEC Grade: 0; SizeAreaWB_mm2: 6.75
R2_P R4_P R7_P R9_P R12_P R16_P R19_P = CMP-0018684-3: RES, 470 k, 5%, 0.25 W, AEC-Q200 Grade 0, 1206; Manufacturer: Vishay-Dale; Power_W: 250mW; TempCo: 200 ppm/C; Value: 470k; EIA_Code: E24; SizeX_mm: 3.2; SizeY_mm: 1.6; SizeZ_mm: 1.35; Value2: 0.25W; SizeArea_mm2: 5.12; AEC Qualified: Y; VDC_V: 200V; AEC Category: Q200; AEC Grade: 0
R3_P R10_P R15_P = CMP-0020842-3: RES, 10.0 k, 1%, 0.125 W, AEC-Q200 Grade 0, 0805; Manufacturer: Vishay-Dale; Power_W: 125mW; TempCo: 100 ppm/C; Value_Code: 10k0; Value: 10.0k; EIA_Code: E96; Res_ohm: 10k; SizeX_mm: 2; SizeY_mm: 1.25; SizeZ_mm: 1.45; Value2: 0.125W; SizeArea_mm2: 2.5; AEC Qualified: Y; VDC_V: 150V; AEC Category: Q200; AEC Grade: 0
R5_P R8_P R13_P R17_P = CMP-0018610-3: RES, 1.0 M, 5%, 0.25 W, AEC-Q200 Grade 0, 1206; Manufacturer: Vishay-Dale; Power_W: 250mW; TempCo: 200 ppm/C; Value_Code: 1M00; Value: 1.0Meg; EIA_Code: E24; Res_ohm: 1M; SizeX_mm: 3.2; SizeY_mm: 1.6; SizeZ_mm: 1.35; Value2: 0.25W; SizeArea_mm2: 5.12; AEC Qualified: Y; VDC_V: 200V; AEC Category: Q200; AEC Grade: 0
R11_P = CMP-0018578-3: RES, 10, 5%, 0.25 W, AEC-Q200 Grade 0, 1206; Manufacturer: Vishay-Dale; Power_W: 250mW; TempCo: 200 ppm/C; Value_Code: 10R0; Value: 10; EIA_Code: E24; SizeX_mm: 3.2; SizeY_mm: 1.6; SizeZ_mm: 1.35; Value2: 0.25W; SizeArea_mm2: 5.12; AEC Qualified: Y; VDC_V: 200V; AEC Category: Q200; AEC Grade: 0
R14_P R200_P = CMP-0018759-2: RES, 0, 5%, 0.25 W, 1206; Manufacturer: Yageo America; Power_W: 250mW; TempCo: 200 ppm/C; Value_Code: 0000; U/M: EA; Value: 0; EIA_Code: E24; SizeX_mm: 3.2; SizeY_mm: 1.6; SizeZ_mm: 1.35; Value2: 0.25W; SizeArea_mm2: 5.12; VDC_V: 200V; AEC Category: Q200
R20_P R36_P R40_P R45_P = CMP-0023153-5: RES, 4.70 k, 1%, 0.1 W, 0603; Manufacturer: Yageo; Power_W: 100mW; TempCo: 100 ppm/C; Value_Code: 4k70; Value: 4.70k; Res_ohm: 4.7k; SizeX_mm: 1.6; SizeY_mm: 0.8; SizeZ_mm: 1; Value2: 0.1W; SizeArea_mm2: 1.28; AEC Qualified: N; VDC_V: 75V; AEC Category: Q200; SizeAreaWB_mm2: 4.68
R21_P = CMP-0022448-4: RES, 49.9, 1%, 0.1 W, AEC-Q200 Grade 0, 0603; Manufacturer: Vishay-Dale; Power_W: 100mW; TempCo: 100 ppm/C; Value_Code: 49R9; Value: 49.9; EIA_Code: E96; SizeX_mm: 1.6; SizeY_mm: 0.8; SizeZ_mm: 1; Value2: 0.1W; SizeArea_mm2: 1.28; AEC Qualified: Y; VDC_V: 75V; AEC Category: Q200; AEC Grade: 0
R22_P = CMP-0018603-3: RES, 1.0 k, 5%, 0.25 W, AEC-Q200 Grade 0, 1206; Manufacturer: Vishay-Dale; Power_W: 250mW; TempCo: 200 ppm/C; Value_Code: 1k00; Value: 1.0k; EIA_Code: E24; Res_ohm: 1k; SizeX_mm: 3.2; SizeY_mm: 1.6; SizeZ_mm: 1.35; Value2: 0.25W; SizeArea_mm2: 5.12; AEC Qualified: Y; VDC_V: 200V; AEC Category: Q200; AEC Grade: 0
R23_P = CMP-0020497-3: RES, 20, 5%, 0.125 W, AEC-Q200 Grade 0, 0805; Manufacturer: Vishay-Dale; Power_W: 125mW; TempCo: 200 ppm/C; Value_Code: 20R0; Value: 20; EIA_Code: E24; SizeX_mm: 2; SizeY_mm: 1.25; SizeZ_mm: 1.45; Value2: 0.125W; SizeArea_mm2: 2.5; AEC Qualified: Y; VDC_V: 150V; AEC Category: Q200; AEC Grade: 0
R24_P = CMP-0022277-4: RES, 2.49 k, 1%, 0.1 W, AEC-Q200 Grade 0, 0603; Manufacturer: Vishay-Dale; Power_W: 100mW; TempCo: 100 ppm/C; Value_Code: 2k49; Value: 2.49k; EIA_Code: E96; SizeX_mm: 1.6; SizeY_mm: 0.8; SizeZ_mm: 1; Value2: 0.1W; SizeArea_mm2: 1.28; AEC Qualified: Y; VDC_V: 75V; AEC Category: Q200; AEC Grade: 0
R25_P = CMP-0023252-5: RES, 6.81 k, 1%, 0.1 W, 0603; Manufacturer: Yageo; Power_W: 100mW; TempCo: 100 ppm/C; Value_Code: 6k81; Value: 6.81k; EIA_Code: E96; SizeX_mm: 1.6; SizeY_mm: 0.8; SizeZ_mm: 1; Value2: 0.1W; SizeArea_mm2: 1.28; AEC Qualified: N; VDC_V: 75V; AEC Category: Q200; SizeAreaWB_mm2: 4.68
R26_P R28_P = CMP-0021759-3: RES, 60.4 k, 1%, 0.125 W, AEC-Q200 Grade 0, 0805; Manufacturer: Panasonic; Power_W: 125mW; TempCo: 100 ppm/C; Value_Code: 60k4; Value: 60.4k; EIA_Code: E96; SizeX_mm: 2; SizeY_mm: 1.25; SizeZ_mm: 1.45; Value2: 0.125W; SizeArea_mm2: 2.5; AEC Qualified: Y; AEC Category: Q200; AEC Grade: 0; SizeAreaWB_mm2: 6.75
R27_P = CMP-0023066-5: RES, 38.3 k, 1%, 0.1 W, 0603; Manufacturer: Yageo; Power_W: 100mW; TempCo: 100 ppm/C; Value_Code: 38k3; Value: 38.3k; EIA_Code: E96; SizeX_mm: 1.6; SizeY_mm: 0.8; SizeZ_mm: 1; Value2: 0.1W; SizeArea_mm2: 1.28; AEC Qualified: N; VDC_V: 75V; AEC Category: Q200; SizeAreaWB_mm2: 4.68
R29_P R32_P R34_P R39_P R41_P = CMP-0022746-5: RES, 10.0 k, 1%, 0.1 W, 0603; Manufacturer: Yageo; Power_W: 100mW; TempCo: 100 ppm/C; Value_Code: 10k0; Value: 10.0k; EIA_Code: E96; Res_ohm: 10k; SizeX_mm: 1.6; SizeY_mm: 0.8; SizeZ_mm: 1; Value2: 0.1W; SizeArea_mm2: 1.28; AEC Qualified: N; VDC_V: 75V; AEC Category: Q200; SizeAreaWB_mm2: 4.68
R30_P = CMP-0021990-4: RES, 100 k, 1%, 0.1 W, AEC-Q200 Grade 0, 0603; Manufacturer: Vishay-Dale; Power_W: 100mW; TempCo: 100 ppm/C; Value: 100k; EIA_Code: E96; SizeX_mm: 1.6; SizeY_mm: 0.8; SizeZ_mm: 1; Value2: 0.1W; SizeArea_mm2: 1.28; AEC Qualified: Y; VDC_V: 75V; AEC Category: Q200; AEC Grade: 0
R31_P = CMP-0023036-5: RES, 33.2 k, 1%, 0.1 W, 0603; Manufacturer: Yageo; Power_W: 100mW; TempCo: 100 ppm/C; Value_Code: 33k2; Value: 33.2k; EIA_Code: E96; SizeX_mm: 1.6; SizeY_mm: 0.8; SizeZ_mm: 1; Value2: 0.1W; SizeArea_mm2: 1.28; AEC Qualified: N; VDC_V: 75V; AEC Category: Q200; SizeAreaWB_mm2: 4.68
R33_P R43_P R44_P = CMP-0022109-5: RES, 1.00 k, 1%, 0.1 W, AEC-Q200 Grade 0, 0603; Manufacturer: Vishay-Dale; Power_W: 100mW; TempCo: 100 ppm/C; Value_Code: 1k00; Value: 1.00k; EIA_Code: E96; Res_ohm: 1k; SizeX_mm: 1.6; SizeY_mm: 0.8; SizeZ_mm: 1; Value2: 0.1W; SizeArea_mm2: 1.28; AEC Qualified: Y; VDC_V: 75V; AEC Category: Q200; AEC Grade: 0
R35_P = CMP-0016530-2: RES, 0.5, 1%, 1 W, 2010; Manufacturer: Stackpole Electronics Inc; Power_W: 1W; TempCo: 250 ppm/C; Value_Code: R500; U/M: EA; Value: 0.5; SizeX_mm: 5; SizeY_mm: 2.5; SizeZ_mm: 1.66; SizeArea_mm2: 12.5; AEC Category: Q200
R37_P = CMP-0023037-5: RES, 33.0 k, 1%, 0.1 W, 0603; Manufacturer: Yageo; Power_W: 100mW; TempCo: 100 ppm/C; Value_Code: 33k0; Value: 33.0k; Res_ohm: 33k; SizeX_mm: 1.6; SizeY_mm: 0.8; SizeZ_mm: 1; Value2: 0.1W; SizeArea_mm2: 1.28; AEC Qualified: N; VDC_V: 75V; AEC Category: Q200; SizeAreaWB_mm2: 4.68
R38_P = CMP-0022478-4: RES, 4.99, 1%, 0.1 W, AEC-Q200 Grade 0, 0603; Manufacturer: Vishay-Dale; Power_W: 100mW; TempCo: 100 ppm/C; Value_Code: 4R99; Value: 4.99; EIA_Code: E96; SizeX_mm: 1.6; SizeY_mm: 0.8; SizeZ_mm: 1; Value2: 0.1W; SizeArea_mm2: 1.28; AEC Qualified: Y; VDC_V: 75V; AEC Category: Q200; AEC Grade: 0
R42_P = CMP-0022762-5: RES, 11.8 k, 1%, 0.1 W, 0603; Manufacturer: Yageo; Power_W: 100mW; TempCo: 100 ppm/C; Value_Code: 11k8; Value: 11.8k; EIA_Code: E96; SizeX_mm: 1.6; SizeY_mm: 0.8; SizeZ_mm: 1; Value2: 0.1W; SizeArea_mm2: 1.28; AEC Qualified: N; VDC_V: 75V; AEC Category: Q200; SizeAreaWB_mm2: 4.68
RT1_P RT2_P RT3_P = CMP-0002556-2: Thermistor NTC, 4.70 ohm, 20%, 8.5mm Disc; Manufacturer: TDK; TaMax_C: 170°C; TaMin_C: -55°C; Power_W: 1.4W; U/M: EA
T1_P = CMP-0094994-1: Tranformer, Flyback, 30W, THT; Manufacturer: Wurth; DCR_ohm: 0.87; Ns1toNp: 4.67:1/6:1/6:1/7:1/1:1; Frequency_Fixed: 40kHz; AEC Qualified: No; Voltage_Isolation_Vrms: 500V; SizeZ_mm: 22.86mm
TP1_P TP2_P TP3_P TP5_P = CMP-0055149-2: Test Point, Multipurpose, White, TH; Manufacturer: Keystone Electronics; ContactFinish: Silver; CT: TRUE; CNHeader: FALSE; Green_Lifecycle: Active; Green_REACh: Passed
TP4_P = CMP-0055147-2: Test Point, Multipurpose, Red, TH; Manufacturer: Keystone Electronics; CT: TRUE; ContactFinish: Silver; Green_Lifecycle: Active; CNHeader: FALSE; Green_REACh: Passed
TP6_P = CMP-0055137-2: Test Point, Miniature, Red, TH; Manufacturer: Keystone Electronics; Green_REACh: Passed; Green_Lifecycle: Active; ContactFinish: Silver; CNHeader: FALSE; CT: TRUE
TP7_P = CMP-0055148-2: Test Point, Multipurpose, Black, TH; Manufacturer: Keystone Electronics; CNHeader: FALSE; ContactFinish: Silver; Green_REACh: Passed; Green_Lifecycle: Active; CT: TRUE
TP8_P = CMP-0055140-2: Test Point, Miniature, Orange, TH; Manufacturer: Keystone Electronics; Green_Lifecycle: Active; ContactFinish: Silver; CNHeader: FALSE; CT: TRUE; Green_REACh: Passed
TP9_P = CMP-0055138-2: Test Point, Miniature, Black, TH; Manufacturer: Keystone Electronics; ContactFinish: Silver; CNHeader: FALSE; Green_Lifecycle: Active; Green_REACh: Passed; CT: TRUE
TP10_P = CMP-0003825-1: 1mm Test Point, SMT; Manufacturer: Any
U1_P = CMP-0013050-3: High-Frequency Multi-Mode Synchronous Rectifier Controller, DBV0005A (SOT-23-5); Manufacturer: Texas Instruments; Alternate PartNumber: UCC24612-1DBVT; SizeX_mm: 2.8; SizeY_mm: 2.9; CompType: IC; SizeZ_mm: 1.45; SizeArea_mm2: 8.12; SizeAreaWB_mm2: 14.82; AEC Category: Q200; AEC Qualified: N
U2_P = CMP-0006177-3: Optocoupler, 5 kV, 80-160% CTR, SMT; Manufacturer: Fairchild Semiconductor; CTR (Max): 160%; CTR (Min): 80%; Voltage_Isolation_Vrms: 5kV
U3_P = CMP-0078369-2: High-Efficiency Low-Cost Flyback Controller with Secondary-Side Regulation, DBV0006A (SOT-23-6); Manufacturer: Texas Instruments; SizeZ_mm: 1.45; SizeX_mm: 2.8; SizeY_mm: 2.9; AEC Category: Q200; AEC Qualified: N; SizeArea_mm2: 8.12; CompType: IC; SizeAreaWB_mm2: 14.82
U4_P = CMP-0033091-1: Adjustable Precision Shunt Regulator, 34 ppm / degC, 100 mA, -40 to 85 degC, 3-pin SOT-23 (DBZ), Green (RoHS & no Sb/Br); Manufacturer: Texas Instruments; Temp Coeff(Typ)(ppm/ degree C): 34; SubFamily: Shunt Voltage Reference; Min Iz for Regulation(uA): 600; Iout/Iz(Max)(mA): 100; VO Adj(Min)(V): 2.495; Rating: Catalog; VO Adj(Max)(V): 36; Temp Coeff(Max)(ppm/ degree C): 92; Initial Accuracy @ 25/deg C(%): 1
U5_P = CMP-0032057-1: Single Supply Voltage Supervisor for 5 V Systems with Programmable Time Delay, 1 Supply Monitored, -40 to 85 degC, 8-pin SOIC (D), Green (RoHS & no Sb/Br); Manufacturer: Texas Instruments; Threshold Voltage 1 (typ)(Typ)(V): 4.55; Output Driver Type / Reset Output: Active-low, Open-drain, Active-high, Open-drain; VCC(Min)(V): 3.5; # of Supplies Monitored: 1; VCC(Max)(V): 18; Rating: Catalog; SubFamily: Supervisor and Reset IC; Iq(Typ)(uA): 1800; Reset Threshold Accuracy(%): 1.1
U6_P = CMP-0066199-1: 2.5V Low Iq Adjustable Precision Shunt Regulator, DBZ0003A (SOT-23-3); Alternate Manufacturer: Texas Instruments; SizeAreaWB_mm2: 14.0; U/M: EA; SizeZ_mm: 1.12; SizeX_mm: 2.5; SizeY_mm: 3.0; SizeArea_mm2: 7.5; CompType: IC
